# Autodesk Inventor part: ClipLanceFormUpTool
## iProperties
Created: 2006-08
Part Number: ClipLanceFormUpTool
Material: Steel
Document SubType Name: Sheet Metal
Designer: CBliss
Author: CBliss
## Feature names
1. Extrusion3
2. Extrusion4
3. Extrusion5
4. Extrusion6
5. Fillet2
6. Extrusion9
7. Plate1
